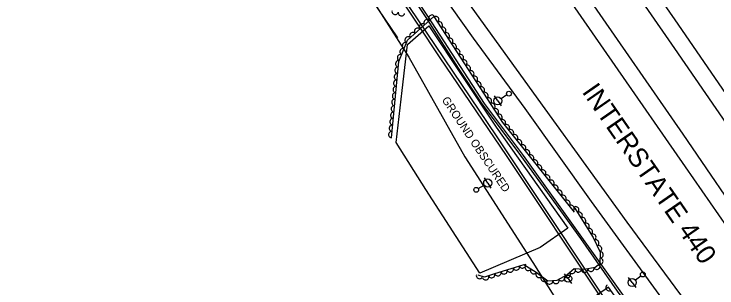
# Model space of a CAD drawing. Extents: x 1722896 to 1754269, y 648279 to 666297.
# Drawn here: x 1731135 to 1731570.5, y 651359.2 to 651528.7 of the extents above; entities that cross this region are included whole.
import ezdxf

# ---------------------------------------------------------------- set-up
doc = ezdxf.new("R2010")
doc.units = 0
for name, color, linetype in [('DESIGN - SCRATCH - User 1', 7, 'Continuous'), ('DESIGN - SHEET - Linework', 7, 'Continuous'), ('SURVEY - CENTERLINE - Preliminary', 7, 'Continuous'), ('SURVEY - CENTERLINE - Preliminary Text', 7, 'Continuous'), ('SURVEY - DTM - Breaklines', 7, 'Continuous'), ('SURVEY - VEGETATION - Features with Text', 7, 'Continuous')]:
    doc.layers.add(name, color=color, linetype=linetype)

msp = doc.modelspace()

# ---------------------------------------------------------------- linework, layer by layer
at = {"layer": 'DESIGN - SCRATCH - User 1'}
for points in [[(1730316.66, 651934.74), (1730384.34, 651932.37), (1730434.04, 651929.34), (1730486.77, 651936.53), (1730564.86, 651948.62), (1730637.45, 651959.62), (1730712.37, 651970.96), (1730787.4, 651982.51), (1730838.1, 651975.69), (1730915.22, 651953.33), (1730985.43, 651933.4), (1731051.32, 651884.1), (1731107.86, 651842.45), (1731151.12, 651814), (1731205.19, 651758.92), (1731241.18, 651722.92), (1731296.03, 651653.13), (1731320.46, 651622.25), (1731363.74, 651557.08), (1731433.62, 651453.34), (1731491.61, 651366.5), (1731532.39, 651305.05)], [(1731531.39, 651304.53), (1731499.82, 651351.65), (1731440.14, 651441.16), (1731398.96, 651501.71), (1731356.67, 651565.56), (1731317.83, 651623.74), (1731275.2, 651677.58), (1731240.37, 651722.35), (1731187.71, 651774.83), (1731150.71, 651812.32), (1731106.55, 651841.58), (1731034.83, 651895.39), (1730985.75, 651931.9), (1730916.62, 651951.71), (1730838.86, 651974.01), (1730787.77, 651981), (1730731.22, 651972.37), (1730648.05, 651959.97), (1730560.32, 651946.66), (1730488.33, 651935.46), (1730433.45, 651928.03), (1730381.68, 651931.42), (1730316.57, 651933.23)], [(1731449.05, 651441.11), (1731424.61, 651473.88), (1731410.41, 651495.25), (1731391.24, 651525.36), (1731366.78, 651561.88), (1731339.73, 651602.43), (1731313.27, 651642.9), (1731292.45, 651667.15), (1731267.16, 651696.4), (1731245.2, 651720.98), (1731207.14, 651762.68), (1731173.65, 651796.5), (1731144.93, 651822.99), (1731146.09, 651823.57), (1731183.63, 651789.17), (1731214.84, 651756.54), (1731256.07, 651710.39), (1731314.12, 651643.8), (1731348.95, 651590.89), (1731391.24, 651527.44), (1731426.33, 651473.42), (1731450.45, 651441.2)], [(1731538.97, 651316.06), (1731508.97, 651357.24), (1731486.14, 651389.77), (1731449.05, 651441.11)], [(1731450.45, 651441.2), (1731487.63, 651389.17), (1731518.62, 651345.9), (1731539.44, 651317.31)]]:
    msp.add_lwpolyline(points, dxfattribs=at)
at = {"layer": 'SURVEY - CENTERLINE - Preliminary'}
msp.add_lwpolyline([(1731390.13, 651420.21), (1731371.8, 651449.19), (1731375.48, 651481.38), (1731378.84, 651509.82), (1731391.91, 651521.47), (1731433.63, 651458.75), (1731478.19, 651396.13), (1731461.07, 651384.36), (1731423.61, 651368.47), (1731390.13, 651420.21)], dxfattribs=at)
at = {"layer": 'SURVEY - CENTERLINE - Preliminary Text'}
for points in [[(1731592.81, 651391.29), (1731549.63, 651454.37), (1731491.17, 651538.79), (1731427.8, 651629.07), (1731385.16, 651689.48), (1731337.8, 651753.25), (1731295.32, 651806.88), (1731249.74, 651861.11), (1731202.94, 651914.16), (1731153.79, 651965.7), (1731107.83, 652011.26), (1731054.55, 652061.78), (1730996.82, 652113.2), (1730942.67, 652157.27), (1730887.56, 652199.54), (1730832.47, 652239.78), (1730770.05, 652283.03), (1730709.42, 652320.26), (1730647.01, 652356.15), (1730588.92, 652388.28)], [(1731616.26, 651421.62), (1731582.91, 651469.74), (1731544.55, 651525.26), (1731504.08, 651583.58), (1731465.63, 651638.51), (1731425.7, 651694.45), (1731391.97, 651740.68), (1731357.02, 651786.85), (1731317.65, 651836.66), (1731283.77, 651876.93), (1731249.46, 651915.96), (1731222.54, 651945.76), (1731197.48, 651972.17), (1731169.27, 652001.13), (1731138.77, 652031.35), (1731108.47, 652060.26)], [(1731118.03, 652036.86), (1731149.54, 652006.15), (1731177.73, 651977.55), (1731213.77, 651940.06), (1731246.05, 651903.81), (1731283.79, 651861.3), (1731321.25, 651815.85), (1731353.39, 651774.59), (1731381.94, 651736.83), (1731409.76, 651698.62), (1731441.81, 651654.07), (1731480.48, 651599.5), (1731509.62, 651557.37), (1731544.16, 651507.36), (1731582.54, 651451.81), (1731609.29, 651412.47)], [(1731115.69, 651989.43), (1731148.06, 651956.9), (1731181.04, 651922.54), (1731209.97, 651890.56), (1731240.98, 651855.7), (1731270.11, 651821.27), (1731301.8, 651782.75), (1731327.55, 651749.5), (1731366.37, 651697.8), (1731400.59, 651650), (1731429.8, 651608.57), (1731465.1, 651557.76), (1731507.25, 651496.97), (1731550.74, 651434.21), (1731586.88, 651382.19)], [(1731558.13, 651341.59), (1731514.92, 651400.01), (1731464.1, 651470.16), (1731410.85, 651543.88), (1731363.06, 651609.61), (1731318.43, 651669.53), (1731283.93, 651713.33), (1731241.74, 651764.26), (1731203.14, 651807.18), (1731173.35, 651838.62), (1731147.09, 651864.95), (1731118.29, 651891.06)], [(1731153.18, 651844.67), (1731163.69, 651833.49), (1731190.66, 651805.52), (1731222.19, 651771.09), (1731247.71, 651740.79), (1731267.38, 651716.8), (1731293.05, 651685.02), (1731315.92, 651655.29), (1731348.4, 651611.98), (1731387.42, 651558.94), (1731419.48, 651513.93), (1731451.49, 651470.32), (1731492.67, 651412.69), (1731536.14, 651352.96), (1731550.85, 651332.66)], [(1731211.31, 651725.73), (1731247.45, 651682.93), (1731281.88, 651645.35), (1731296.06, 651625.43), (1731332.91, 651575.21), (1731379.7, 651502.01), (1731414.28, 651440.47), (1731456.51, 651374.98), (1731481.51, 651335.3), (1731515.69, 651283.68)]]:
    msp.add_lwpolyline(points, dxfattribs=at)
at = {"layer": 'SURVEY - DTM - Breaklines'}
for p, q in [((1731434.7, 651475), (1731432.66, 651478.15)), ((1731440.36, 651478.67), (1731436.8, 651476.36)), ((1731434.7, 651475), (1731436.73, 651471.85)), ((1731428.48, 651424.18), (1731426.57, 651427.41)), ((1731428.48, 651424.18), (1731430.38, 651420.95)), ((1731422.66, 651420.75), (1731426.32, 651422.91)), ((1731478.25, 651364.98), (1731476.05, 651368.02)), ((1731478.25, 651364.98), (1731480.45, 651361.95)), ((1731517.98, 651362.58), (1731515.74, 651365.59)), ((1731523.4, 651366.61), (1731519.99, 651364.07)), ((1731517.98, 651362.58), (1731520.22, 651359.57))]:
    msp.add_line(p, q, dxfattribs=at)
for centre, radius in [((1731441.62, 651479.48), 1.5), ((1731434.7, 651475), 2.5), ((1731428.48, 651424.18), 2.5), ((1731421.37, 651419.98), 1.5), ((1731478.25, 651364.98), 2.25), ((1731524.6, 651367.51), 1.5), ((1731517.98, 651362.58), 2.5)]:
    msp.add_circle(centre, radius, dxfattribs=at)
at = {"layer": 'SURVEY - VEGETATION - Features with Text'}
for points in [[(1731372.82, 651513.99), (1731341.01, 651561.01), (1731310.03, 651607.08), (1731291.34, 651636.96)], [(1731368.77, 651452.16), (1731373.36, 651499.33), (1731378.88, 651512.52), (1731395.08, 651527.34), (1731437.64, 651461.58), (1731482.14, 651406.03)], [(1731482.02, 651409.3), (1731493.86, 651390.37), (1731498.25, 651381.46), (1731498.02, 651374.21), (1731495.15, 651371.8), (1731488.19, 651370.57), (1731482.11, 651371.05), (1731477.78, 651367.39), (1731471.3, 651363.82), (1731465.71, 651363.34), (1731458.57, 651368.8), (1731450.81, 651373.62), (1731442.76, 651370.97), (1731432.76, 651367.97), (1731426.57, 651365.89), (1731422.47, 651367.08)], [(1731534.79, 651315.28), (1731503.39, 651359.78), (1731480.23, 651343.52), (1731473.62, 651324.07), (1731507.66, 651284.86)]]:
    msp.add_lwpolyline(points, dxfattribs=at)
for centre, major_axis in [((1731371.14, 651530.34), (-1.95, 0.43)), ((1731375.05, 651529.48), (-1.95, 0.43)), ((1731393.86, 651526.23), (1.48, 1.35)), ((1731390.91, 651523.53), (1.48, 1.35)), ((1731396.36, 651525.36), (1.09, -1.68)), ((1731398.53, 651522), (1.09, -1.68)), ((1731385.01, 651518.13), (1.48, 1.35)), ((1731387.96, 651520.83), (1.48, 1.35)), ((1731400.7, 651518.64), (1.09, -1.68)), ((1731382.06, 651515.43), (1.48, 1.35)), ((1731402.88, 651515.29), (1.09, -1.68)), ((1731377.46, 651509.11), (0.77, 1.84)), ((1731379.11, 651512.73), (1.48, 1.35)), ((1731405.05, 651511.93), (1.09, -1.68)), ((1731407.22, 651508.57), (1.09, -1.68)), ((1731375.91, 651505.42), (0.77, 1.84)), ((1731409.4, 651505.21), (1.09, -1.68)), ((1731374.37, 651501.73), (0.77, 1.84)), ((1731411.57, 651501.85), (1.09, -1.68)), ((1731373.23, 651497.94), (0.19, 1.99)), ((1731413.74, 651498.5), (1.09, -1.68)), ((1731372.84, 651493.96), (0.19, 1.99)), ((1731415.92, 651495.14), (1.09, -1.68)), ((1731418.09, 651491.78), (1.09, -1.68)), ((1731372.45, 651489.98), (0.19, 1.99)), ((1731420.27, 651488.42), (1.09, -1.68)), ((1731372.07, 651486), (0.19, 1.99)), ((1731422.44, 651485.06), (1.09, -1.68)), ((1731371.68, 651482.02), (0.19, 1.99)), ((1731424.61, 651481.71), (1.09, -1.68)), ((1731426.79, 651478.35), (1.09, -1.68)), ((1731370.9, 651474.05), (0.19, 1.99)), ((1731371.29, 651478.04), (0.19, 1.99)), ((1731428.96, 651474.99), (1.09, -1.68)), ((1731370.52, 651470.07), (0.19, 1.99)), ((1731431.13, 651471.63), (1.09, -1.68)), ((1731370.13, 651466.09), (0.19, 1.99)), ((1731433.31, 651468.27), (1.09, -1.68)), ((1731369.74, 651462.11), (0.19, 1.99)), ((1731435.48, 651464.92), (1.09, -1.68)), ((1731437.66, 651461.56), (1.25, -1.56)), ((1731369.35, 651458.13), (0.19, 1.99)), ((1731440.16, 651458.44), (1.25, -1.56)), ((1731368.97, 651454.15), (0.19, 1.99)), ((1731442.66, 651455.32), (1.25, -1.56)), ((1731445.16, 651452.2), (1.25, -1.56)), ((1731447.66, 651449.07), (1.25, -1.56)), ((1731450.16, 651445.95), (1.25, -1.56)), ((1731452.66, 651442.83), (1.25, -1.56)), ((1731455.16, 651439.71), (1.25, -1.56)), ((1731457.66, 651436.59), (1.25, -1.56)), ((1731460.16, 651433.46), (1.25, -1.56)), ((1731462.66, 651430.34), (1.25, -1.56)), ((1731465.17, 651427.22), (1.25, -1.56)), ((1731467.67, 651424.1), (1.25, -1.56)), ((1731470.17, 651420.98), (1.25, -1.56)), ((1731472.67, 651417.86), (1.25, -1.56)), ((1731475.17, 651414.73), (1.25, -1.56)), ((1731477.67, 651411.61), (1.25, -1.56)), ((1731480.17, 651408.49), (1.25, -1.56)), ((1731483.08, 651407.6), (1.06, -1.7)), ((1731485.2, 651404.21), (1.06, -1.7)), ((1731487.33, 651400.82), (1.06, -1.7)), ((1731489.45, 651397.43), (1.06, -1.7)), ((1731491.57, 651394.04), (1.06, -1.7)), ((1731493.69, 651390.65), (1.06, -1.7)), ((1731495.48, 651387.07), (0.88, -1.79)), ((1731497.25, 651383.48), (0.88, -1.79)), ((1731498.19, 651379.72), (-0.06, -2)), ((1731498.06, 651375.72), (-0.06, -2)), ((1731442.47, 651370.89), (-1.92, -0.57)), ((1731446.27, 651372.13), (-1.9, -0.62)), ((1731450.07, 651373.38), (-1.9, -0.62)), ((1731453.55, 651371.92), (-1.7, 1.06)), ((1731492.44, 651371.32), (-1.97, -0.35)), ((1731496.11, 651372.61), (-1.53, -1.29)), ((1731423.37, 651366.82), (-1.92, 0.56)), ((1731430.99, 651367.38), (-1.9, -0.64)), ((1731434.81, 651368.59), (-1.92, -0.57)), ((1731438.64, 651369.74), (-1.92, -0.57)), ((1731456.94, 651369.81), (-1.7, 1.06)), ((1731460.23, 651367.53), (-1.59, 1.21)), ((1731477.85, 651367.45), (-1.53, -1.29)), ((1731480.9, 651370.03), (-1.53, -1.29)), ((1731484.52, 651370.86), (-1.99, 0.16)), ((1731488.5, 651370.63), (-1.97, -0.35)), ((1731427.2, 651366.11), (-1.9, -0.64)), ((1731463.41, 651365.11), (-1.59, 1.21)), ((1731466.81, 651363.44), (-1.99, -0.17)), ((1731470.79, 651363.78), (-1.99, -0.17)), ((1731474.36, 651365.5), (-1.75, -0.96)), ((1731503.66, 651359.4), (-1.15, 1.63))]:
    msp.add_ellipse(centre, major_axis=major_axis, ratio=0.940188, start_param=0, end_param=3.141593, dxfattribs=at)

# ---------------------------------------------------------------- texts
at = {"layer": 'DESIGN - SHEET - Linework'}
msp.add_text('INTERSTATE 440', height=12, rotation=304.715, dxfattribs=at).set_placement((1731486.51, 651480.59))
at = {"layer": 'SURVEY - CENTERLINE - Preliminary'}
msp.add_text('GROUND OBSCURED', height=5, rotation=303.9565, dxfattribs=at).set_placement((1731399.79, 651475.57))

doc.saveas('drawing.dxf')
